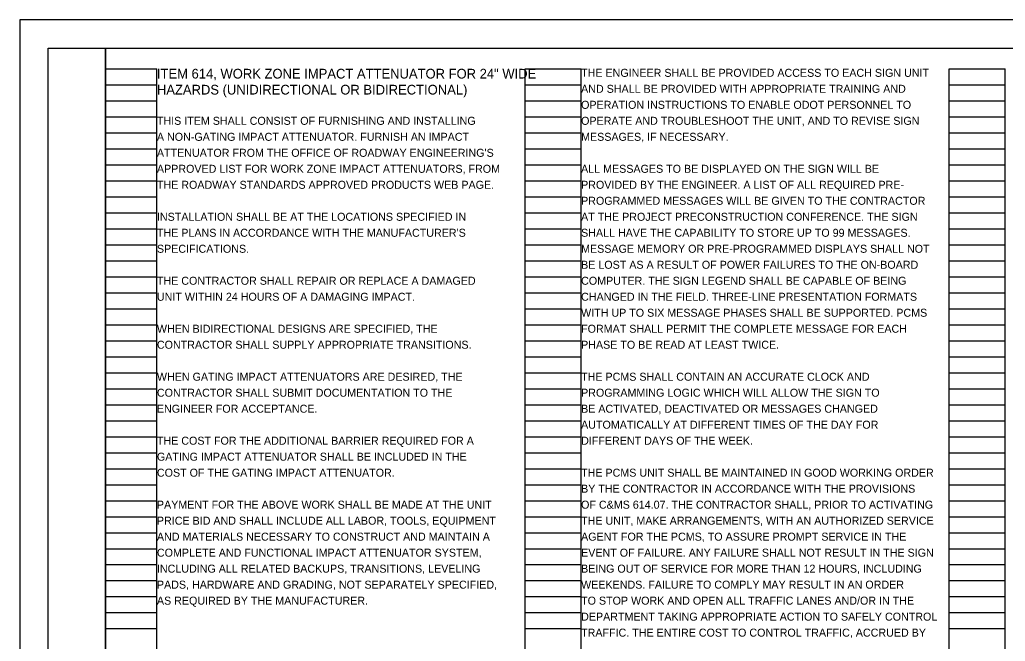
# Model space of a CAD drawing. Extents: x 0 to 34, y -31.6 to -9.6.
# Drawn here: x 0 to 17.24, y -20.5 to -9.62 of the extents above; entities that cross this region are included whole.
import ezdxf

# ---------------------------------------------------------------- set-up
doc = ezdxf.new("R2010")
doc.units = 0
for name, color, linetype in [('SH_Border', 7, 'Continuous'), ('SH_Cut_Line', 7, 'Continuous'), ('SH_Data', 7, 'Continuous'), ('SH_Text', 7, 'Continuous')]:
    doc.layers.add(name, color=color, linetype=linetype)

msp = doc.modelspace()

# ---------------------------------------------------------------- linework, layer by layer
at = {"layer": 'SH_Border'}
for points in [[(0.5, -10.117), (1.5, -10.117), (1.5, -31.117), (0.5, -31.117)], [(1.5, -10.117), (33.5, -10.117), (33.5, -31.117), (1.5, -31.117)]]:
    msp.add_lwpolyline(points, close=True, dxfattribs=at)
at = {"layer": 'SH_Cut_Line'}
msp.add_lwpolyline([(0, -31.617), (34, -31.617), (34, -9.617), (0, -9.617)], close=True, dxfattribs=at)
at = {"layer": 'SH_Data'}
for p, q in [((1.5, -30.637), (1.5, -10.477)), ((1.5, -10.477), (2.4, -10.477)), ((2.4, -30.637), (2.4, -10.477)), ((8.84, -30.637), (8.84, -10.477)), ((8.84, -10.477), (9.82, -10.477)), ((9.82, -30.637), (9.82, -10.477)), ((16.26, -30.637), (16.26, -10.477)), ((16.26, -10.477), (17.24, -10.477)), ((17.24, -30.637), (17.24, -10.477)), ((1.5, -10.757), (2.4, -10.757)), ((8.84, -10.757), (9.82, -10.757)), ((16.26, -10.757), (17.24, -10.757)), ((1.5, -11.037), (2.4, -11.037)), ((8.84, -11.037), (9.82, -11.037)), ((16.26, -11.037), (17.24, -11.037)), ((1.5, -11.317), (2.4, -11.317)), ((8.84, -11.317), (9.82, -11.317)), ((16.26, -11.317), (17.24, -11.317)), ((1.5, -11.597), (2.4, -11.597)), ((8.84, -11.597), (9.82, -11.597)), ((16.26, -11.597), (17.24, -11.597)), ((1.5, -11.877), (2.4, -11.877)), ((8.84, -11.877), (9.82, -11.877)), ((16.26, -11.877), (17.24, -11.877)), ((1.5, -12.157), (2.4, -12.157)), ((8.84, -12.157), (9.82, -12.157)), ((16.26, -12.157), (17.24, -12.157)), ((1.5, -12.437), (2.4, -12.437)), ((8.84, -12.437), (9.82, -12.437)), ((16.26, -12.437), (17.24, -12.437)), ((1.5, -12.717), (2.4, -12.717)), ((8.84, -12.717), (9.82, -12.717)), ((16.26, -12.717), (17.24, -12.717)), ((1.5, -12.997), (2.4, -12.997)), ((8.84, -12.997), (9.82, -12.997)), ((16.26, -12.997), (17.24, -12.997)), ((1.5, -13.277), (2.4, -13.277)), ((8.84, -13.277), (9.82, -13.277)), ((16.26, -13.277), (17.24, -13.277)), ((1.5, -13.557), (2.4, -13.557)), ((8.84, -13.557), (9.82, -13.557)), ((16.26, -13.557), (17.24, -13.557)), ((1.5, -13.837), (2.4, -13.837)), ((8.84, -13.837), (9.82, -13.837)), ((16.26, -13.837), (17.24, -13.837)), ((1.5, -14.117), (2.4, -14.117)), ((8.84, -14.117), (9.82, -14.117)), ((16.26, -14.117), (17.24, -14.117)), ((1.5, -14.397), (2.4, -14.397)), ((8.84, -14.397), (9.82, -14.397)), ((16.26, -14.397), (17.24, -14.397)), ((1.5, -14.677), (2.4, -14.677)), ((8.84, -14.677), (9.82, -14.677)), ((16.26, -14.677), (17.24, -14.677)), ((1.5, -14.957), (2.4, -14.957)), ((8.84, -14.957), (9.82, -14.957)), ((16.26, -14.957), (17.24, -14.957)), ((1.5, -15.237), (2.4, -15.237)), ((8.84, -15.237), (9.82, -15.237)), ((16.26, -15.237), (17.24, -15.237)), ((1.5, -15.517), (2.4, -15.517)), ((8.84, -15.517), (9.82, -15.517)), ((16.26, -15.517), (17.24, -15.517)), ((1.5, -15.797), (2.4, -15.797)), ((8.84, -15.797), (9.82, -15.797)), ((16.26, -15.797), (17.24, -15.797)), ((1.5, -16.077), (2.4, -16.077)), ((8.84, -16.077), (9.82, -16.077)), ((16.26, -16.077), (17.24, -16.077)), ((1.5, -16.357), (2.4, -16.357)), ((8.84, -16.357), (9.82, -16.357)), ((16.26, -16.357), (17.24, -16.357)), ((1.5, -16.637), (2.4, -16.637)), ((8.84, -16.637), (9.82, -16.637)), ((16.26, -16.637), (17.24, -16.637)), ((1.5, -16.917), (2.4, -16.917)), ((8.84, -16.917), (9.82, -16.917)), ((16.26, -16.917), (17.24, -16.917)), ((1.5, -17.197), (2.4, -17.197)), ((8.84, -17.197), (9.82, -17.197)), ((16.26, -17.197), (17.24, -17.197)), ((1.5, -17.477), (2.4, -17.477)), ((8.84, -17.477), (9.82, -17.477)), ((16.26, -17.477), (17.24, -17.477)), ((1.5, -17.757), (2.4, -17.757)), ((8.84, -17.757), (9.82, -17.757)), ((16.26, -17.757), (17.24, -17.757)), ((1.5, -18.037), (2.4, -18.037)), ((8.84, -18.037), (9.82, -18.037)), ((16.26, -18.037), (17.24, -18.037)), ((1.5, -18.317), (2.4, -18.317)), ((8.84, -18.317), (9.82, -18.317)), ((16.26, -18.317), (17.24, -18.317)), ((1.5, -18.597), (2.4, -18.597)), ((8.84, -18.597), (9.82, -18.597)), ((16.26, -18.597), (17.24, -18.597)), ((1.5, -18.877), (2.4, -18.877)), ((8.84, -18.877), (9.82, -18.877)), ((16.26, -18.877), (17.24, -18.877)), ((1.5, -19.157), (2.4, -19.157)), ((8.84, -19.157), (9.82, -19.157)), ((16.26, -19.157), (17.24, -19.157)), ((1.5, -19.437), (2.4, -19.437)), ((8.84, -19.437), (9.82, -19.437)), ((16.26, -19.437), (17.24, -19.437)), ((1.5, -19.717), (2.4, -19.717)), ((8.84, -19.717), (9.82, -19.717)), ((16.26, -19.717), (17.24, -19.717)), ((1.5, -19.997), (2.4, -19.997)), ((8.84, -19.997), (9.82, -19.997)), ((16.26, -19.997), (17.24, -19.997)), ((1.5, -20.277), (2.4, -20.277)), ((8.84, -20.277), (9.82, -20.277)), ((16.26, -20.277), (17.24, -20.277))]:
    msp.add_line(p, q, dxfattribs=at)

# ---------------------------------------------------------------- texts
at = {"layer": 'SH_Text'}
for s, height, p in [('ITEM 614, WORK ZONE IMPACT ATTENUATOR FOR 24" WIDE', 0.17, (2.4, -10.647)), ('THE ENGINEER SHALL BE PROVIDED ACCESS TO EACH SIGN UNIT', 0.14, (9.82, -10.617)), ('HAZARDS (UNIDIRECTIONAL OR BIDIRECTIONAL)', 0.17, (2.4, -10.927)), ('AND SHALL BE PROVIDED WITH APPROPRIATE TRAINING AND', 0.14, (9.82, -10.897)), ('OPERATION INSTRUCTIONS TO ENABLE ODOT PERSONNEL TO', 0.14, (9.82, -11.177)), ('THIS ITEM SHALL CONSIST OF FURNISHING AND INSTALLING', 0.14, (2.4, -11.457)), ('OPERATE AND TROUBLESHOOT THE UNIT, AND TO REVISE SIGN', 0.14, (9.82, -11.457)), ('A NON-GATING IMPACT ATTENUATOR. FURNISH AN IMPACT', 0.14, (2.4, -11.737)), ('MESSAGES, IF NECESSARY.', 0.14, (9.82, -11.737)), ("ATTENUATOR FROM THE OFFICE OF ROADWAY ENGINEERING'S", 0.14, (2.4, -12.017)), ('APPROVED LIST FOR WORK ZONE IMPACT ATTENUATORS, FROM', 0.14, (2.4, -12.297)), ('ALL MESSAGES TO BE DISPLAYED ON THE SIGN WILL BE', 0.14, (9.82, -12.297)), ('THE ROADWAY STANDARDS APPROVED PRODUCTS WEB PAGE.', 0.14, (2.4, -12.577)), ('PROVIDED BY THE ENGINEER. A LIST OF ALL REQUIRED PRE-', 0.14, (9.82, -12.577)), ('PROGRAMMED MESSAGES WILL BE GIVEN TO THE CONTRACTOR', 0.14, (9.82, -12.857)), ('INSTALLATION SHALL BE AT THE LOCATIONS SPECIFIED IN', 0.14, (2.4, -13.137)), ('AT THE PROJECT PRECONSTRUCTION CONFERENCE. THE SIGN', 0.14, (9.82, -13.137)), ("THE PLANS IN ACCORDANCE WITH THE MANUFACTURER'S", 0.14, (2.4, -13.417)), ('SHALL HAVE THE CAPABILITY TO STORE UP TO 99 MESSAGES.', 0.14, (9.82, -13.417)), ('SPECIFICATIONS.', 0.14, (2.4, -13.697)), ('MESSAGE MEMORY OR PRE-PROGRAMMED DISPLAYS SHALL NOT', 0.14, (9.82, -13.697)), ('BE LOST AS A RESULT OF POWER FAILURES TO THE ON-BOARD', 0.14, (9.82, -13.977)), ('THE CONTRACTOR SHALL REPAIR OR REPLACE A DAMAGED', 0.14, (2.4, -14.257)), ('COMPUTER. THE SIGN LEGEND SHALL BE CAPABLE OF BEING', 0.14, (9.82, -14.257)), ('UNIT WITHIN 24 HOURS OF A DAMAGING IMPACT.', 0.14, (2.4, -14.537)), ('CHANGED IN THE FIELD. THREE-LINE PRESENTATION FORMATS', 0.14, (9.82, -14.537)), ('WITH UP TO SIX MESSAGE PHASES SHALL BE SUPPORTED. PCMS', 0.14, (9.82, -14.817)), ('WHEN BIDIRECTIONAL DESIGNS ARE SPECIFIED, THE', 0.14, (2.4, -15.097)), ('FORMAT SHALL PERMIT THE COMPLETE MESSAGE FOR EACH', 0.14, (9.82, -15.097)), ('CONTRACTOR SHALL SUPPLY APPROPRIATE TRANSITIONS.', 0.14, (2.4, -15.377)), ('PHASE TO BE READ AT LEAST TWICE.', 0.14, (9.82, -15.377)), ('WHEN GATING IMPACT ATTENUATORS ARE DESIRED, THE', 0.14, (2.4, -15.937)), ('THE PCMS SHALL CONTAIN AN ACCURATE CLOCK AND', 0.14, (9.82, -15.937)), ('CONTRACTOR SHALL SUBMIT DOCUMENTATION TO THE', 0.14, (2.4, -16.217)), ('PROGRAMMING LOGIC WHICH WILL ALLOW THE SIGN TO', 0.14, (9.82, -16.217)), ('ENGINEER FOR ACCEPTANCE.', 0.14, (2.4, -16.497)), ('BE ACTIVATED, DEACTIVATED OR MESSAGES CHANGED', 0.14, (9.82, -16.497)), ('AUTOMATICALLY AT DIFFERENT TIMES OF THE DAY FOR', 0.14, (9.82, -16.777)), ('THE COST FOR THE ADDITIONAL BARRIER REQUIRED FOR A', 0.14, (2.4, -17.057)), ('DIFFERENT DAYS OF THE WEEK.', 0.14, (9.82, -17.057)), ('GATING IMPACT ATTENUATOR SHALL BE INCLUDED IN THE', 0.14, (2.4, -17.337)), ('COST OF THE GATING IMPACT ATTENUATOR.', 0.14, (2.4, -17.617)), ('THE PCMS UNIT SHALL BE MAINTAINED IN GOOD WORKING ORDER', 0.14, (9.82, -17.617)), ('BY THE CONTRACTOR IN ACCORDANCE WITH THE PROVISIONS', 0.14, (9.82, -17.897)), ('PAYMENT FOR THE ABOVE WORK SHALL BE MADE AT THE UNIT', 0.14, (2.4, -18.177)), ('OF C&MS 614.07. THE CONTRACTOR SHALL, PRIOR TO ACTIVATING', 0.14, (9.82, -18.177)), ('PRICE BID AND SHALL INCLUDE ALL LABOR, TOOLS, EQUIPMENT', 0.14, (2.4, -18.457)), ('THE UNIT, MAKE ARRANGEMENTS, WITH AN AUTHORIZED SERVICE', 0.14, (9.82, -18.457)), ('AND MATERIALS NECESSARY TO CONSTRUCT AND MAINTAIN A', 0.14, (2.4, -18.737)), ('AGENT FOR THE PCMS, TO ASSURE PROMPT SERVICE IN THE', 0.14, (9.82, -18.737)), ('COMPLETE AND FUNCTIONAL IMPACT ATTENUATOR SYSTEM,', 0.14, (2.4, -19.017)), ('EVENT OF FAILURE. ANY FAILURE SHALL NOT RESULT IN THE SIGN', 0.14, (9.82, -19.017)), ('INCLUDING ALL RELATED BACKUPS, TRANSITIONS, LEVELING', 0.14, (2.4, -19.297)), ('BEING OUT OF SERVICE FOR MORE THAN 12 HOURS, INCLUDING', 0.14, (9.82, -19.297)), ('PADS, HARDWARE AND GRADING, NOT SEPARATELY SPECIFIED,', 0.14, (2.4, -19.577)), ('WEEKENDS. FAILURE TO COMPLY MAY RESULT IN AN ORDER', 0.14, (9.82, -19.577)), ('AS REQUIRED BY THE MANUFACTURER.', 0.14, (2.4, -19.857)), ('TO STOP WORK AND OPEN ALL TRAFFIC LANES AND/OR IN THE', 0.14, (9.82, -19.857)), ('DEPARTMENT TAKING APPROPRIATE ACTION TO SAFELY CONTROL', 0.14, (9.82, -20.137)), ('TRAFFIC. THE ENTIRE COST TO CONTROL TRAFFIC, ACCRUED BY', 0.14, (9.82, -20.417))]:
    msp.add_text(s, height=height, dxfattribs=at).set_placement(p)

doc.saveas('drawing.dxf')
